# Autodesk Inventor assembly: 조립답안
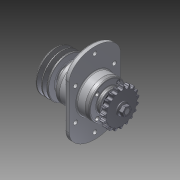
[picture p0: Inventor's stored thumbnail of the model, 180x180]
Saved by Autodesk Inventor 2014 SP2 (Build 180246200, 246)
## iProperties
Created: 2015-02
Part Number: 조립답안
Document SubType Name: Assembly
Designer: 201-09
Author: 201-09
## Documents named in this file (12)
- C:\Users\201-09\Desktop\450207V1011\조립답안.iam
- C:\Users\201-09\Desktop\450207V1011\1-본체.ipt
- C:\Users\201-09\Desktop\450207V1011\6-베어링 6206.ipt
- C:\Users\201-09\Desktop\450207V1011\7-부시.ipt
- C:\Users\201-09\Desktop\450207V1011\2-커버.ipt
- C:\Users\201-09\Desktop\450207V1011\8-오일실 30x42.ipt
- C:\Users\201-09\Desktop\450207V1011\10-M6.ipt
- C:\Users\201-09\Desktop\450207V1011\9-M16-너트.ipt
- C:\Users\201-09\Desktop\450207V1011\3-축.ipt
- C:\Users\201-09\Desktop\450207V1011\11-키 6x6.ipt
- C:\Users\201-09\Desktop\450207V1011\4-V벨트풀리.ipt
- C:\Users\201-09\Desktop\450207V1011\5-체인 스프로킷.ipt
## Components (20 placed, 11 different names)
1. 1-본체:1 — 플러쉬:1
2. 6-베어링 6206:1
3. 6-베어링 6206:2
4. 7-부시:1 — 플러쉬:1
5. 2-커버:1
6. 2-커버:2
7. 8-8-오일실 30x42:1
8. 8-8-오일실 30x42:2
9. 10-M6:2
10. 9-M16 너트:1
11. 9-M16 너트:2
12. 3-축:1
13. 11-키 6x6:1
14. 11-키 6x6:2
15. 4-V벨트풀리:1
16. 5-체인 스프로킷:1
17. 10-M6:1
18. 10-M6:3
19. 10-M6:4
20. 10-M6:5
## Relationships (1: Flush 1)
- 플러쉬:1 [Flush]: 1-본체:1 ↔ 7-부시:1
